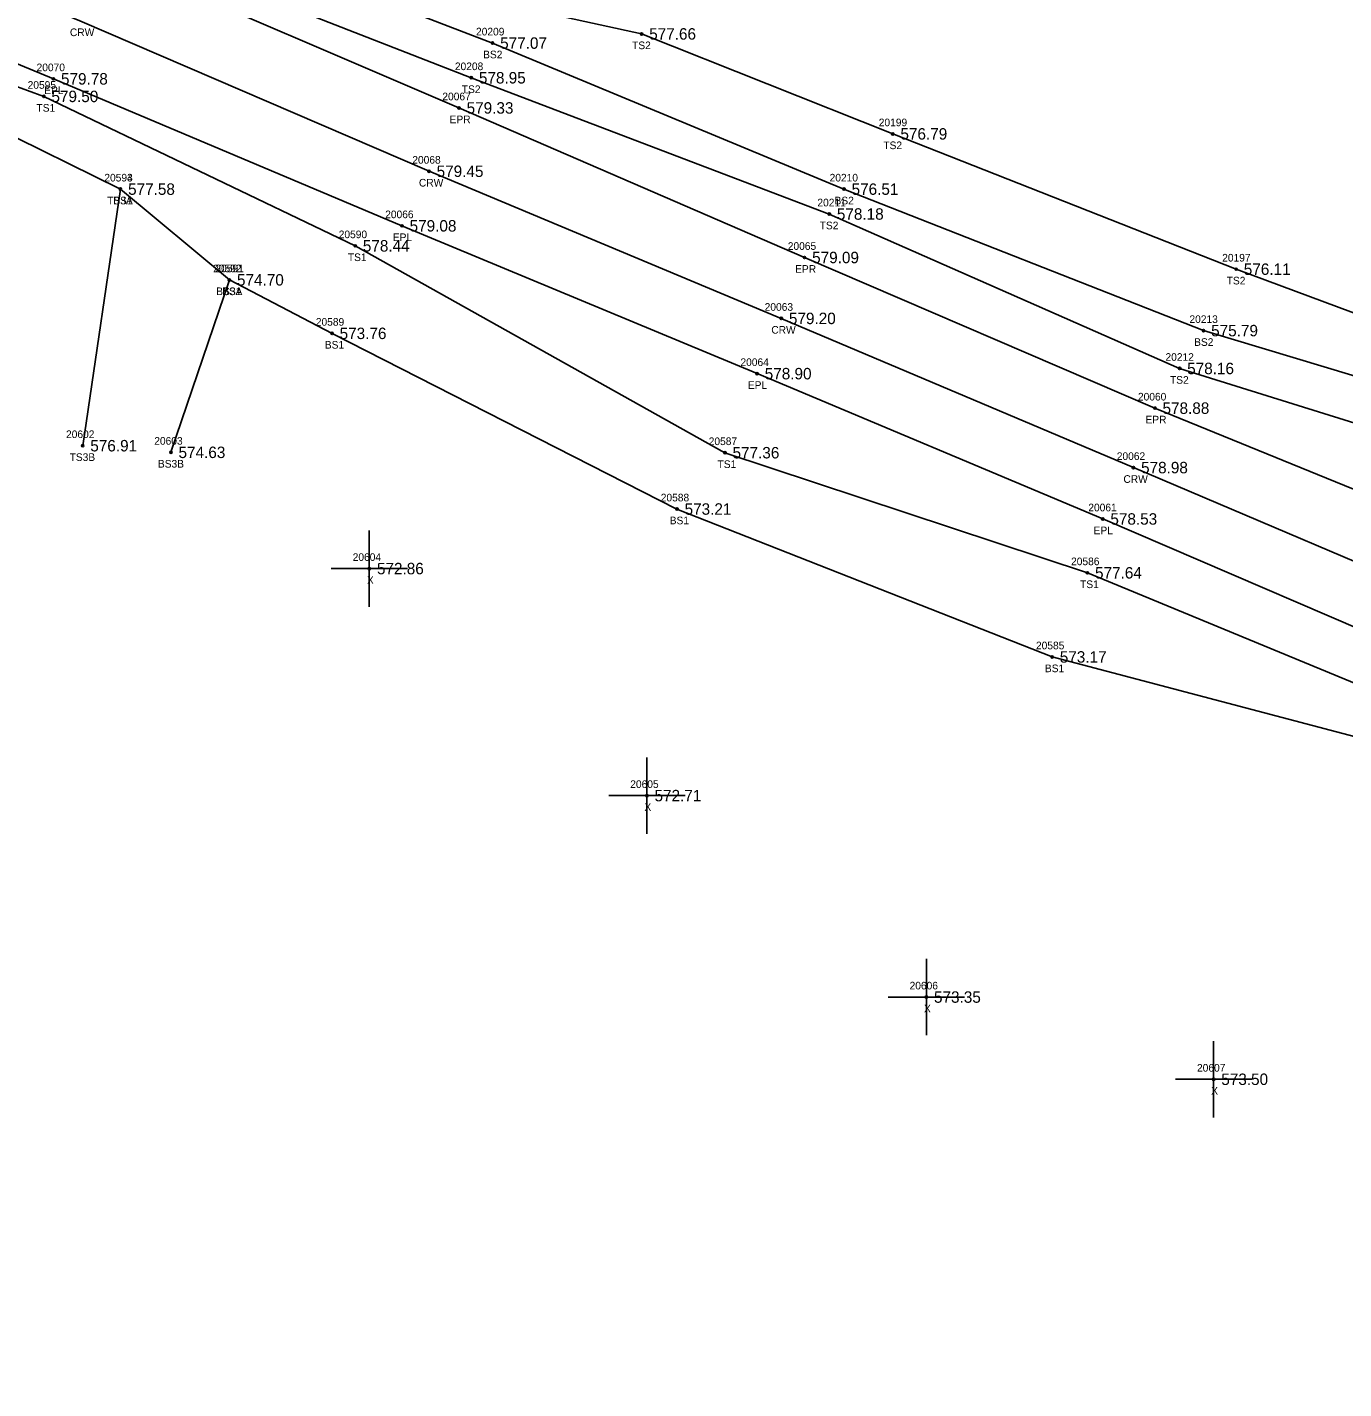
# Model space of a CAD drawing. Extents: x 1664837 to 1666270, y 987403 to 988245.
# Drawn here: x 1665140.5 to 1665313, y 987738.3 to 987916.7 of the extents above; entities that cross this region are included whole.
import ezdxf

# ---------------------------------------------------------------- set-up
doc = ezdxf.new("R2010")
doc.units = 0
for name, color, linetype in [('RD_DTM_BkLn1', 7, 'Continuous'), ('RD_DTM_BkLn2', 7, 'Continuous'), ('RD_DTM_BkLn_txCode', 7, 'Continuous'), ('RD_EX_Misc', 7, 'Continuous'), ('RD_EX_Misc_txCode', 7, 'Continuous'), ('RD_EX_Road', 7, 'Continuous'), ('RD_EX_Road_txCode', 7, 'Continuous'), ('RD_EX_TX_Misc_ELEV', 7, 'Continuous'), ('RD_EX_TX_Road_ELEV', 7, 'Continuous'), ('RD_HC_Survey_ELEV', 7, 'Continuous'), ('RD_HC_Survey_txCode', 7, 'Continuous'), ('RD_SMD_Locator', 7, 'Continuous')]:
    doc.layers.add(name, color=color, linetype=linetype)

msp = doc.modelspace()

# ---------------------------------------------------------------- linework, layer by layer
at = {"layer": 'RD_DTM_BkLn1'}
msp.add_lwpolyline([(1665502.18, 987767.43), (1665469.18, 987781.68), (1665423.29, 987801.23), (1665377.17, 987820.37), (1665331.28, 987839.54), (1665285.44, 987859.03), (1665239.3, 987878.58), (1665193.14, 987897.86), (1665147.41, 987917.57), (1665101.07, 987936.7), (1665055.19, 987956.08), (1665009.23, 987975.83), (1664963.42, 987995.66), (1664917.15, 988015.07), (1664871.41, 988034.69)], dxfattribs=at)
at = {"layer": 'RD_DTM_BkLn2'}
for p, q in [((1665152.71, 987895.52), (1665147.76, 987861.9)), ((1665166.98, 987883.63), (1665159.32, 987861.03))]:
    msp.add_line(p, q, dxfattribs=at)
for points in [[(1665526.5, 987797.57), (1665466.88, 987821.13), (1665430.93, 987834.67), (1665385.41, 987852.45), (1665344.34, 987868.11), (1665298.9, 987885.03), (1665253.91, 987902.76), (1665220.99, 987915.86), (1665188.5, 987922.98), (1665151.7, 987937.17), (1665150.15, 987932.64), (1665154.49, 987927.34), (1665198.68, 987910.11), (1665245.58, 987892.26), (1665291.48, 987872.02), (1665339.41, 987857.06), (1665385.96, 987838.24), (1665430.55, 987820.66), (1665476.41, 987799.7), (1665510.35, 987785.06), (1665506.66, 987778.89)], [(1665151.94, 987933.71), (1665201.46, 987914.66), (1665247.51, 987895.52), (1665294.62, 987876.98), (1665342.05, 987862.7), (1665388.78, 987843.93), (1665435.12, 987827.47), (1665481.62, 987807.44), (1665516.85, 987790.52)], [(1665497.35, 987756.86), (1665493.15, 987755.47), (1665489.09, 987748.98), (1665474.07, 987754.55), (1665461.3, 987759.68), (1665416.12, 987784.47), (1665369.46, 987807.94), (1665325.7, 987826.1), (1665279.41, 987845.24), (1665231.91, 987860.98), (1665183.47, 987888.09), (1665142.67, 987907.67), (1665119.08, 987916.32), (1665106.25, 987916.18)], [(1665485.84, 987738.32), (1665468.07, 987746.27), (1665459.94, 987754.9), (1665412.19, 987777.99), (1665366.38, 987802.17), (1665323.99, 987821.27), (1665274.79, 987834.22), (1665225.63, 987853.6), (1665180.43, 987876.62), (1665166.98, 987883.63), (1665152.71, 987895.52), (1665118.68, 987912.3), (1665108.44, 987911.82), (1665107.08, 987900.15)]]:
    msp.add_lwpolyline(points, dxfattribs=at)
at = {"layer": 'RD_EX_Misc'}
for p, q in [((1665185.32, 987840.8), (1665185.32, 987850.8)), ((1665180.32, 987845.8), (1665190.32, 987845.8)), ((1665221.69, 987811.05), (1665221.69, 987821.05)), ((1665216.69, 987816.05), (1665226.69, 987816.05)), ((1665258.31, 987784.65), (1665258.31, 987794.65)), ((1665253.31, 987789.65), (1665263.31, 987789.65)), ((1665295.95, 987773.88), (1665295.95, 987783.88)), ((1665290.95, 987778.88), (1665300.95, 987778.88))]:
    msp.add_line(p, q, dxfattribs=at)
at = {"layer": 'RD_EX_Road'}
for points in [[(1665506.06, 987776.52), (1665471.95, 987789.57), (1665426.52, 987809.19), (1665380.33, 987828.78), (1665335.61, 987847.53), (1665288.25, 987866.82), (1665242.34, 987886.56), (1665197.07, 987906.16), (1665152.2, 987925.43), (1665127.55, 987936.7), (1665104.5, 987945.2), (1665059.19, 987965.3), (1665013.63, 987984.66), (1664966.38, 988005.06), (1664921.66, 988023.83), (1664875.55, 988043.8)], [(1665498.75, 987759.37), (1665465.87, 987774.2), (1665419.78, 987793.88), (1665373.62, 987813.14), (1665327.95, 987832.31), (1665281.42, 987852.3), (1665236.13, 987871.34), (1665189.6, 987890.71), (1665143.92, 987909.97), (1665117.43, 987920.99), (1665086.22, 987934.27), (1665051.62, 987948.55), (1665005.38, 987968.44), (1664960.17, 987987.67), (1664913.53, 988007.62), (1664868.21, 988026.81)]]:
    msp.add_lwpolyline(points, dxfattribs=at)
at = {"layer": 'RD_SMD_Locator'}
for centre in [(1665201.46, 987914.66), (1665220.99, 987915.86), (1665143.92, 987909.97), (1665198.68, 987910.11), (1665142.67, 987907.67), (1665197.07, 987906.16), (1665253.91, 987902.76), (1665193.14, 987897.86), (1665152.71, 987895.52), (1665152.71, 987895.52), (1665247.51, 987895.52), (1665245.58, 987892.26), (1665189.6, 987890.71), (1665183.47, 987888.09), (1665242.34, 987886.56), (1665298.9, 987885.03), (1665166.98, 987883.63), (1665166.98, 987883.63), (1665239.3, 987878.58), (1665294.62, 987876.98), (1665180.43, 987876.62), (1665291.48, 987872.02), (1665236.13, 987871.34), (1665288.25, 987866.82), (1665147.76, 987861.9), (1665159.32, 987861.03), (1665231.91, 987860.98), (1665285.44, 987859.03), (1665225.63, 987853.6), (1665281.42, 987852.3), (1665185.32, 987845.8), (1665279.41, 987845.24), (1665274.79, 987834.22), (1665221.69, 987816.05), (1665258.31, 987789.65), (1665295.95, 987778.88)]:
    msp.add_circle(centre, 0.15, dxfattribs=at)

# ---------------------------------------------------------------- texts
at = {"layer": 'RD_DTM_BkLn_txCode'}
for s, p in [('20209', (1665199.3, 987915.66)), ('TS2', (1665219.75, 987913.86)), ('BS2', (1665200.23, 987912.66)), ('20208', (1665196.53, 987911.11)), ('20595', (1665140.55, 987908.67)), ('TS2', (1665197.44, 987908.11)), ('TS1', (1665141.71, 987905.67)), ('20199', (1665252.07, 987903.76)), ('TS2', (1665252.67, 987900.76)), ('20593', (1665150.6, 987896.52)), ('20594', (1665150.6, 987896.52)), ('20210', (1665245.63, 987896.52)), ('TS3A', (1665150.98, 987893.52)), ('BS1', (1665151.77, 987893.52)), ('20211', (1665244.03, 987893.26)), ('BS2', (1665246.28, 987893.52)), ('20590', (1665181.31, 987889.09)), ('TS2', (1665244.33, 987890.26)), ('TS1', (1665182.51, 987886.09)), ('20197', (1665297.07, 987886.03)), ('20592', (1665164.86, 987884.63)), ('20591', (1665165.15, 987884.63)), ('BS3A', (1665165.26, 987881.63)), ('BS1', (1665166.04, 987881.63)), ('TS2', (1665297.66, 987883.03)), ('20213', (1665292.78, 987877.98)), ('20589', (1665178.31, 987877.62)), ('BS1', (1665179.49, 987874.62)), ('BS2', (1665293.39, 987874.98)), ('20212', (1665289.64, 987873.02)), ('TS2', (1665290.23, 987870.02)), ('20602', (1665145.58, 987862.9)), ('20603', (1665157.14, 987862.03)), ('20587', (1665229.79, 987861.98)), ('TS3B', (1665146.05, 987859.9)), ('BS3B', (1665157.62, 987859.03)), ('TS1', (1665230.95, 987858.98)), ('20588', (1665223.51, 987854.6)), ('BS1', (1665224.68, 987851.6)), ('20586', (1665277.27, 987846.24)), ('TS1', (1665278.45, 987843.24)), ('20585', (1665272.67, 987835.22)), ('BS1', (1665273.84, 987832.22))]:
    msp.add_text(s, height=1, dxfattribs=at).set_placement(p)
at = {"layer": 'RD_EX_Misc_txCode'}
for s, p in [('20604', (1665183.14, 987846.8)), ('X', (1665185.01, 987843.8)), ('20605', (1665219.51, 987817.05)), ('X', (1665221.37, 987814.05)), ('20606', (1665256.11, 987790.65)), ('X', (1665258, 987787.65)), ('20607', (1665293.77, 987779.88)), ('X', (1665295.63, 987776.88))]:
    msp.add_text(s, height=1, dxfattribs=at).set_placement(p)
at = {"layer": 'RD_EX_Road_txCode'}
for s, p in [('20070', (1665141.72, 987910.97)), ('EPL', (1665142.72, 987907.97)), ('20067', (1665194.89, 987907.16)), ('EPR', (1665195.84, 987904.16)), ('20066', (1665187.4, 987891.71)), ('EPL', (1665188.4, 987888.71)), ('20065', (1665240.15, 987887.56)), ('EPR', (1665241.11, 987884.56)), ('20064', (1665233.95, 987872.34)), ('EPL', (1665234.92, 987869.34)), ('20060', (1665286.03, 987867.82)), ('EPR', (1665287.02, 987864.82)), ('20061', (1665279.53, 987853.3)), ('EPL', (1665280.22, 987850.3))]:
    msp.add_text(s, height=1, dxfattribs=at).set_placement(p)
at = {"layer": 'RD_EX_TX_Misc_ELEV'}
for s, p in [('577.66', (1665221.99, 987915.11)), ('577.07', (1665202.46, 987913.91)), ('578.95', (1665199.68, 987909.36)), ('579.50', (1665143.67, 987906.92)), ('576.79', (1665254.91, 987902.01)), ('577.58', (1665153.71, 987894.77)), ('577.58', (1665153.71, 987894.77)), ('576.51', (1665248.51, 987894.77)), ('578.18', (1665246.58, 987891.51)), ('578.44', (1665184.47, 987887.34)), ('574.70', (1665167.98, 987882.88)), ('574.70', (1665167.98, 987882.88)), ('576.11', (1665299.9, 987884.28)), ('573.76', (1665181.43, 987875.87)), ('575.79', (1665295.62, 987876.23)), ('578.16', (1665292.48, 987871.27)), ('576.91', (1665148.76, 987861.15)), ('574.63', (1665160.32, 987860.28)), ('577.36', (1665232.91, 987860.23)), ('573.21', (1665226.63, 987852.85)), ('572.86', (1665186.32, 987845.05)), ('577.64', (1665280.41, 987844.49)), ('573.17', (1665275.79, 987833.47)), ('572.71', (1665222.69, 987815.3)), ('573.35', (1665259.31, 987788.9)), ('573.50', (1665296.95, 987778.13))]:
    msp.add_text(s, height=1.5, dxfattribs=at).set_placement(p)
at = {"layer": 'RD_EX_TX_Road_ELEV'}
for s, p in [('579.78', (1665144.92, 987909.22)), ('579.33', (1665198.07, 987905.41)), ('579.08', (1665190.6, 987889.96)), ('579.09', (1665243.34, 987885.81)), ('578.90', (1665237.13, 987870.59)), ('578.88', (1665289.25, 987866.07)), ('578.53', (1665282.42, 987851.55))]:
    msp.add_text(s, height=1.5, dxfattribs=at).set_placement(p)
at = {"layer": 'RD_HC_Survey_ELEV'}
for s, p in [('579.45', (1665194.14, 987897.11)), ('579.20', (1665240.3, 987877.83)), ('578.98', (1665286.44, 987858.28))]:
    msp.add_text(s, height=1.5, dxfattribs=at).set_placement(p)
at = {"layer": 'RD_HC_Survey_txCode'}
for s, p in [('CRW', (1665146.09, 987915.57)), ('20068', (1665190.95, 987898.86)), ('CRW', (1665191.82, 987895.86)), ('20063', (1665237.12, 987879.58)), ('CRW', (1665237.99, 987876.58)), ('20062', (1665283.26, 987860.03)), ('CRW', (1665284.13, 987857.03))]:
    msp.add_text(s, height=1, dxfattribs=at).set_placement(p)

doc.saveas('drawing.dxf')
